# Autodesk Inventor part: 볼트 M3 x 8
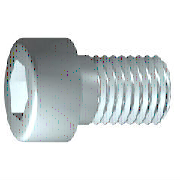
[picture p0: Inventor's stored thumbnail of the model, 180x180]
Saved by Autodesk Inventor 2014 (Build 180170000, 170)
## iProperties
IsCustomPart: 0
Created: 2012-02
Part Number: 볼트 M3 x 8
Material: 스테인리스강
Description: 6각 소켓 머리 캡 나사
Document SubType Name: Modeling
Standard: ISO 4762
Designer: mduedu
Standard Revision: Fourth edition 2004-03-01
Standards Organization: ISO
Language: ko-KR
Size Designation: M3 x 8
Categories: <MemberInstance><Categories><Category DisplayName="조임쇠" InternalName="e4da775c-781d-43d5-af7c-5136215cf5a6" Mnemonic="FSTN"><Category DisplayName="볼트" InternalN
Density: 8.08 g/cm^3
Mass: 0.955869 g
Surface Area: 1.83001 cm^2
Volume: 0.118301 cm^3
Appearance: 반광택
Author: mduedu
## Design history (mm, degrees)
sketch "스케치1"
  geometry: L1 (-0.867, 0)-(8, 0); L2 (8, 0)-(8, 1.5); L3 (8, 1.5)-(1.25, 1.5); L4 (1.25, 1.5)-(0.943, 1.5); L5 (0.943, 1.5)-(0, 1.5); L6 (0, 1.5)-(0, 2.75); L7 (0, 2.75)-(-3, 2.75); L8 (-3, 2.75)-(-3, 1.443); L9 (-3, 1.443)-(-1.7, 1.443); L10 (-1.7, 1.443)-(-0.867, 0); L11 (-5.2, 0)-(10.2, 0) reference; L12 (0, -0.55)-(0, 3.3) reference; L13 (1.25, 1.5)-(0, 1.5)
  constraints: 22 end point, 6 parallel, 2 collinear, 2 perpendicular, 1 horizontal, 1 point on line
  dimensions: "d1" = 6.75 distance from line of L3.end L2 (= GEL); "d2" = 0.30683 distance of L4.end L3.end (computed from GAL); "d3" = 3 distance between parallel lines of L8 L6 (= KOH); "d4" = 1.3 distance of L8.end L9.end (= INTI); "d5" = 60 deg angle of L10 L1; "d6" = 3 diameter of L3 L1 (= GD); "d7" = 3 diameter of L5 L1 (= BDM); "d8" = 2.88675 diameter of L9 L1 (= 1.1547 x SW); "d9" = 5.5 diameter of L7 L1 (= KOD); "d26" = 8 distance between parallel lines of L12 L2 (= NLG)
revolve "본체" sketch "스케치1" stored, may be unused: angle "d10" = 90 deg
sketch "스케치2"
  geometry: L1 (0, -3.85)-(0, 3.85) reference; L2 (-3.85, 0)-(3.85, 0) reference; L3 (1.443, 0)-(0.722, -1.25); L4 (0.722, -1.25)-(-0.722, -1.25); L5 (-0.722, -1.25)-(-1.443, 0); L6 (-1.443, 0)-(-0.722, 1.25); L7 (-0.722, 1.25)-(0.722, 1.25); L8 (0.722, 1.25)-(1.443, 0); 2 further points
  constraints: 12 end point, 1 coincident, 1 horizontal alignment, 1 point on line, 12 other
extrude "슬롯" join sketch "스케치2" stored distance "d11" = 10; taper "d12" = 0 deg
workplane "Work Plane1"
fillet "Fillet2" dims "d30" = 0.1 (= R)
body "Solid1"
fillet "모깎기1" dims "d17" = 0.3 (= RR)
feature "스레드" dims "d13" = 6.75 (= GEL), "d14" = 0
chamfer "모따기1" distance "d15" = 0.30673 (= -0.5 x SPD + 0.5 x GD); stored, may be unused: second distance "d16" = 0.30673 (= GUL), angle "d27" = 45 deg
other parameters: "GD" = 3 [user parameter; used in 2 equation terms], "NLG" = 8 [user parameter; used in 1 equation term], "GEL" = 6.75 [user parameter; used in 2 equation terms], "KOD" = 5.5 [user parameter; used in 1 equation term], "KOH" = 3 [user parameter; used in 1 equation term], "INTI" = 1.3 [user parameter; used in 1 equation term], "GAL" = 0.30673 (= 0.61345 x PTC) [user parameter; used in 1 equation term], "GUL" = 0.30673 (= 0.61345 x PTC) [user parameter; used in 1 equation term], "BDM" = 3 (= NND) [user parameter; used in 1 equation term], "SW" = 2.5 [user parameter; used in 2 equation terms], "RR" = 0.3 [user parameter; used in 1 equation term], "SPD" = 2.38655 (= NND - 1.2269 x PTC) [user parameter; used in 1 equation term], "d19" = 0, "d28" = 0, "d29" = 0, "R" = 0.1 [user parameter; used in 1 equation term], "TOA" = 30 deg [user parameter], "GD1" = 2.38655 (= THREADDIA - 1.2269 x PTC) [user parameter], "THREADDIA" = 3 [user parameter; used in 1 equation term], "FAWI" = 45 deg [user parameter], "PTC" = 0.5 [user parameter; used in 5 equation terms], "NND" = 3 [user parameter; used in 2 equation terms], "E0" = 2.8875 (= 1.155 x SW) [user parameter]
